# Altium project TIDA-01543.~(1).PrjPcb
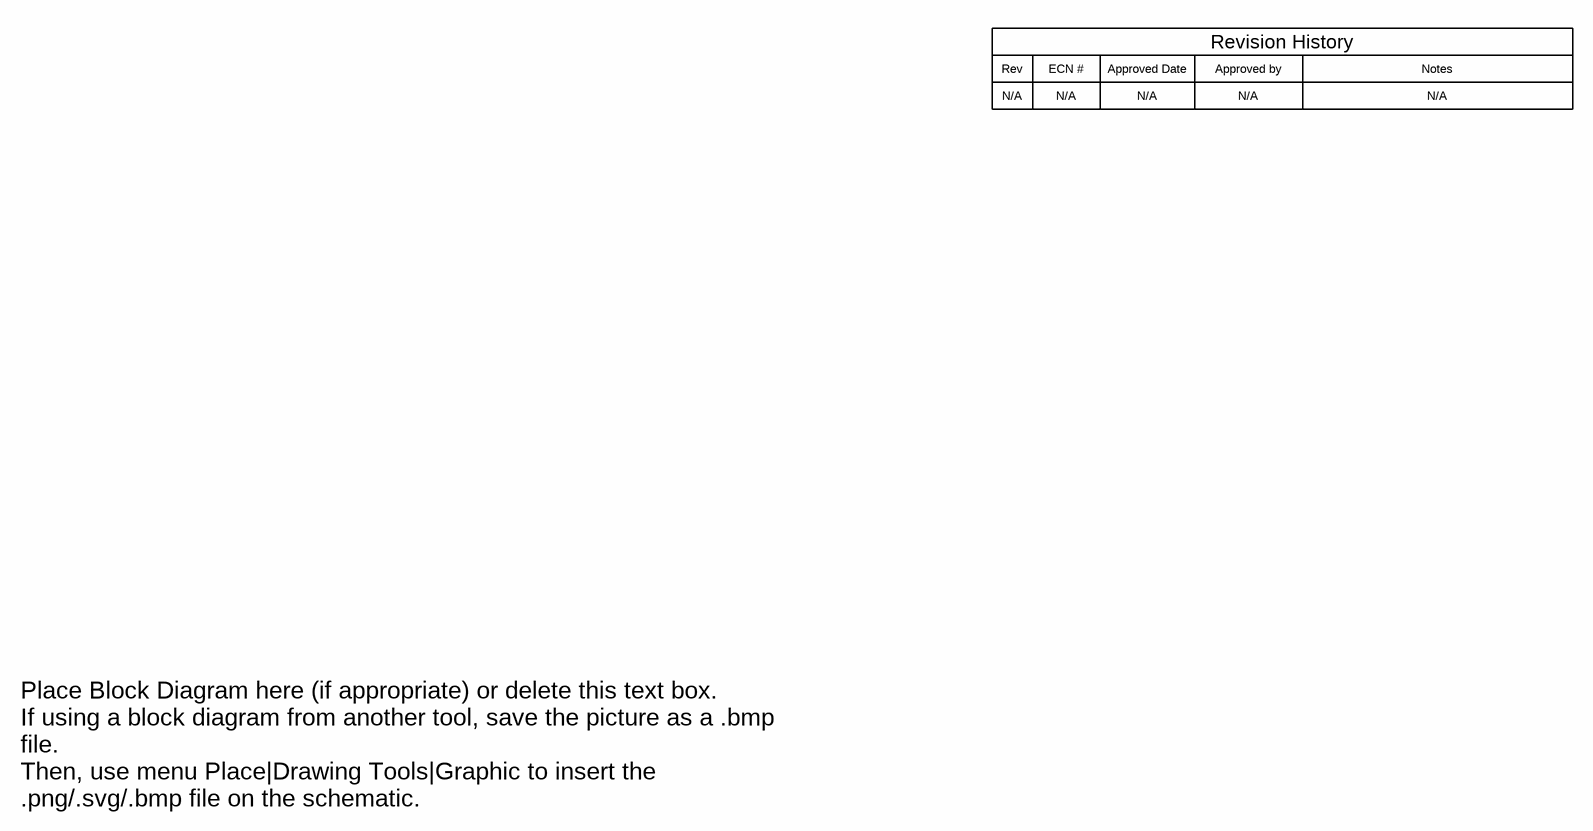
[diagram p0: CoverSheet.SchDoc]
TID: N/A; TechSupport: http://www.ti.com/support; SCH_Rev: E1; PRJ_Title: ±300A Isolated Current Sense for Traction Inverter with Overcurrent Detection; PRJ_Number: TIDA-01543; PRJ_Engineer: S. M.; PRJ_Customer: Public Release; PCB_Rev: A1; PCB_Layout: S. M.; CopyrightYear: 2017
3 sheets, 59 parts. Net scope: flat (ports and power ports of the same name join across sheets).
Board file: PCB.PcbDoc
Sheets:
  CoverSheet.SchDoc
  EVM_Hardware.SchDoc
  EVM_Main.SchDoc

## Sheet CoverSheet.SchDoc
size 431 x 279 mm; Date: Not shown in title block; ApprovedBy: Not shown in title block; CheckedBy: Not shown in title block; Author: Not shown in title block; CompanyName: Not shown in title block; Engineer: Not shown in title block; Organization: Not shown in title block; Address1: Not shown in title block; Address2: Not shown in title block; Address3: Not shown in title block; Address4: Not shown in title block; DocumentNumber: 1; Revision: Use project parameter SCH_Rev; SheetNumber: 1; SheetTotal: 3; PageSetup: Record=PageOptions¦CenterHorizontal=True¦CenterVertical=True¦PrintScale=1.00¦XCorrection=1.00¦YCorrection=1.00¦PrintKind=0¦BorderSize=5000000¦LeftOffset=0¦BottomOffset=0¦Orientation=2¦PaperLength=1000¦PaperWidth=1000¦Scale=100¦PaperSource=15¦PrintQuality=600¦MediaType=1¦DitherType=10¦PaperKind=Letter¦PrintScaleMode=1

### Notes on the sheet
- Rev
- N/A
- ECN #
- Approved Date
- Approved by
- Revision History
- Notes
- Place Block Diagram here (if appropriate) or delete this text box.
  If using a block diagram from another tool, save the picture as a .bmp file.
  Then, use menu Place|Drawing Tools|Graphic to insert the .png/.svg/.bmp file on the schematic.

## Sheet EVM_Hardware.SchDoc
size 431 x 279 mm; Date: Not shown in title block; ApprovedBy: Not shown in title block; CheckedBy: Not shown in title block; Author: Not shown in title block; CompanyName: Not shown in title block; Engineer: Not shown in title block; Organization: Not shown in title block; Address1: Not shown in title block; Address2: Not shown in title block; Address3: Not shown in title block; Address4: Not shown in title block; DocumentNumber: 1; Revision: Use project parameter SCH_Rev; SheetNumber: 3; SheetTotal: 3; PageSetup: Record=PageOptions¦CenterHorizontal=True¦CenterVertical=True¦PrintScale=1.00¦XCorrection=1.00¦YCorrection=1.00¦PrintKind=0¦BorderSize=5000000¦LeftOffset=0¦BottomOffset=0¦Orientation=2¦PaperLength=1000¦PaperWidth=1000¦Scale=100¦PaperSource=15¦PrintQuality=600¦MediaType=1¦DitherType=10¦PaperKind=Letter¦PrintScaleMode=1
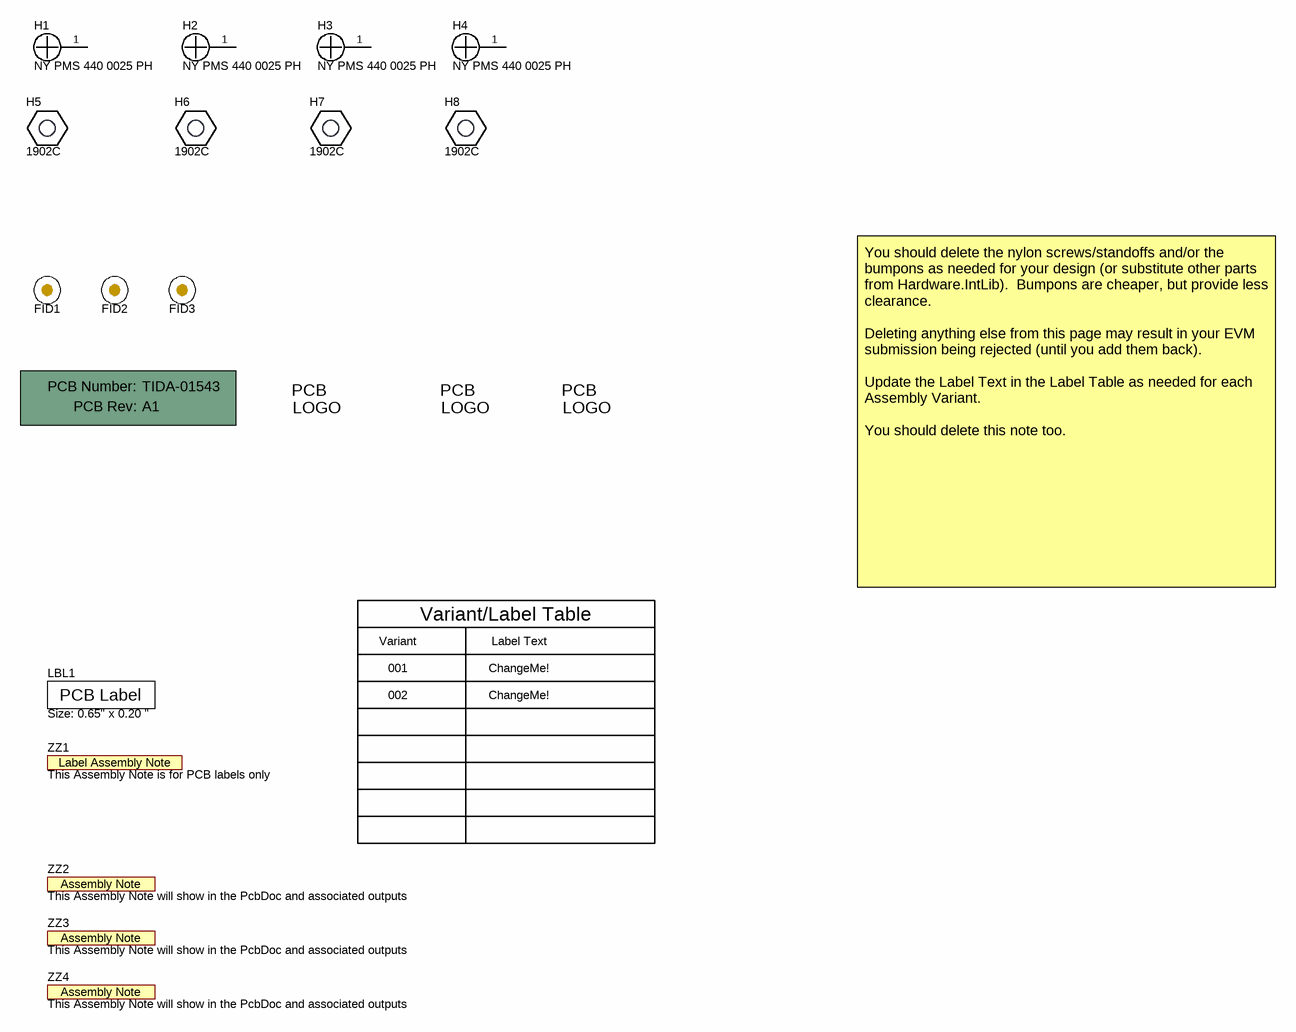
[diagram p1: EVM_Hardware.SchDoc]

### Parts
!PCB1  Printed Circuit Board  (value not drawn)  (mechanical)
FID1  Fiducial  [Fiducial10-20]  (value not drawn)
FID2  Fiducial  [Fiducial10-20]  (value not drawn)
FID3  Fiducial  [Fiducial10-20]  (value not drawn)
H1  NY PMS 440 0025 PH  [NY PMS 440 0025 PH]
H2  NY PMS 440 0025 PH  [NY PMS 440 0025 PH]
H3  NY PMS 440 0025 PH  [NY PMS 440 0025 PH]
H4  NY PMS 440 0025 PH  [NY PMS 440 0025 PH]
H5  1902C  [Keystone_1902C]
H6  1902C  [Keystone_1902C]
H7  1902C  [Keystone_1902C]
H8  1902C  [Keystone_1902C]
LBL1  Size: 0.65" x 0.20 "  [Label_650x200]
Logo1  Texas Instruments  [TI_Stacked_Overlay_Small]  (value not drawn)  (no BOM)
Logo2  Pb-Free Symbol  [Pb-Free_Overlay_Small]  (value not drawn)  (no BOM)
Logo3  FCC disclaimer  [FCC_disclaimer]  (value not drawn)  (no BOM)
ZZ1  This Assembly Note is for PCB labels only  [AssemblyNoteLabel]  (no BOM)
ZZ2  This Assembly Note will show in the PcbDoc and associated outputs  [AssemblyNote]  (no BOM)
ZZ3  This Assembly Note will show in the PcbDoc and associated outputs  [AssemblyNote]  (no BOM)
ZZ4  This Assembly Note will show in the PcbDoc and associated outputs  [AssemblyNote]  (no BOM)

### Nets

Not connected (* = marked no-connect by the designer): H1 1; H2 1; H3 1; H4 1

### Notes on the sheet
- Variant
- Variant/Label Table
- Label Text
- You should delete the nylon screws/standoffs and/or the bumpons as needed for your design (or substitute other parts from Hardware.IntLib).  Bumpons are cheaper, but provide less clearance.
  Deleting anything else from this page may result in your EVM submission being rejected (until you add them back).
  Update the Label Text in the Label Table as needed for each Assembly Variant.
  You should delete this note too.
- 001
- 002
- ChangeMe!

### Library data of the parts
!PCB1 = PCB: Manufacturer: Any; PartNumber: TIDA-01543; SymbolCreator: a0412235
FID1-FID3 = Fiducial: Fiducial mark.  There is nothing to buy or mount.; SymbolCreator: codlsc
H1-H4 = NY PMS 440 0025 PH: Machine Screw, Round, #4-40 x 1/4, Nylon, Philips panhead; Manufacturer: B&F Fastener Supply; CompType: Hardware; SymbolCreator: codlsc; U/M: EA; Green_Lifecycle: Not Set; Green_REACh: Incomplete
H5-H8 = 1902C: Standoff, Hex, 0.5"L #4-40 Nylon; Manufacturer: Keystone; Green_Lifecycle: Active; Green_REACh: Passed; SymbolCreator: a0412235
LBL1 = THT-14-423-10: Thermal Transfer Printable Labels, 0.650" W x 0.200" H - 10,000 per roll; Manufacturer: Brady; SymbolCreator: a0412235; CompType: Label; Green_Lifecycle: Not Set; Green_REACh: Incomplete
Logo1 = TI_Logo: Texas Instrument Corporate Signature; SymbolCreator: a0412235
Logo2 = Pb-Free: SymbolCreator: a0412235
Logo3 = FCC_disclaimer: SymbolCreator: a0412235
ZZ1 = AssemblyNoteLabel: SymbolCreator: a0412235
ZZ2-ZZ4 = AssemblyNote: SymbolCreator: codlsc

## Sheet EVM_Main.SchDoc
size 431 x 279 mm; Date: Not shown in title block; ApprovedBy: Not shown in title block; CheckedBy: Not shown in title block; Author: Not shown in title block; CompanyName: Not shown in title block; Engineer: Not shown in title block; Organization: Not shown in title block; Address1: Not shown in title block; Address2: Not shown in title block; Address3: Not shown in title block; Address4: Not shown in title block; DocumentNumber: 1; Revision: Use project parameter SCH_Rev; SheetNumber: 2; SheetTotal: 3; PageSetup: Record=PageOptions¦CenterHorizontal=True¦CenterVertical=True¦PrintScale=1.00¦XCorrection=1.00¦YCorrection=1.00¦PrintKind=0¦BorderSize=5000000¦LeftOffset=0¦BottomOffset=0¦Orientation=2¦PaperLength=1000¦PaperWidth=1000¦Scale=100¦PaperSource=15¦PrintQuality=600¦MediaType=1¦DitherType=10¦PaperKind=Letter¦PrintScaleMode=1
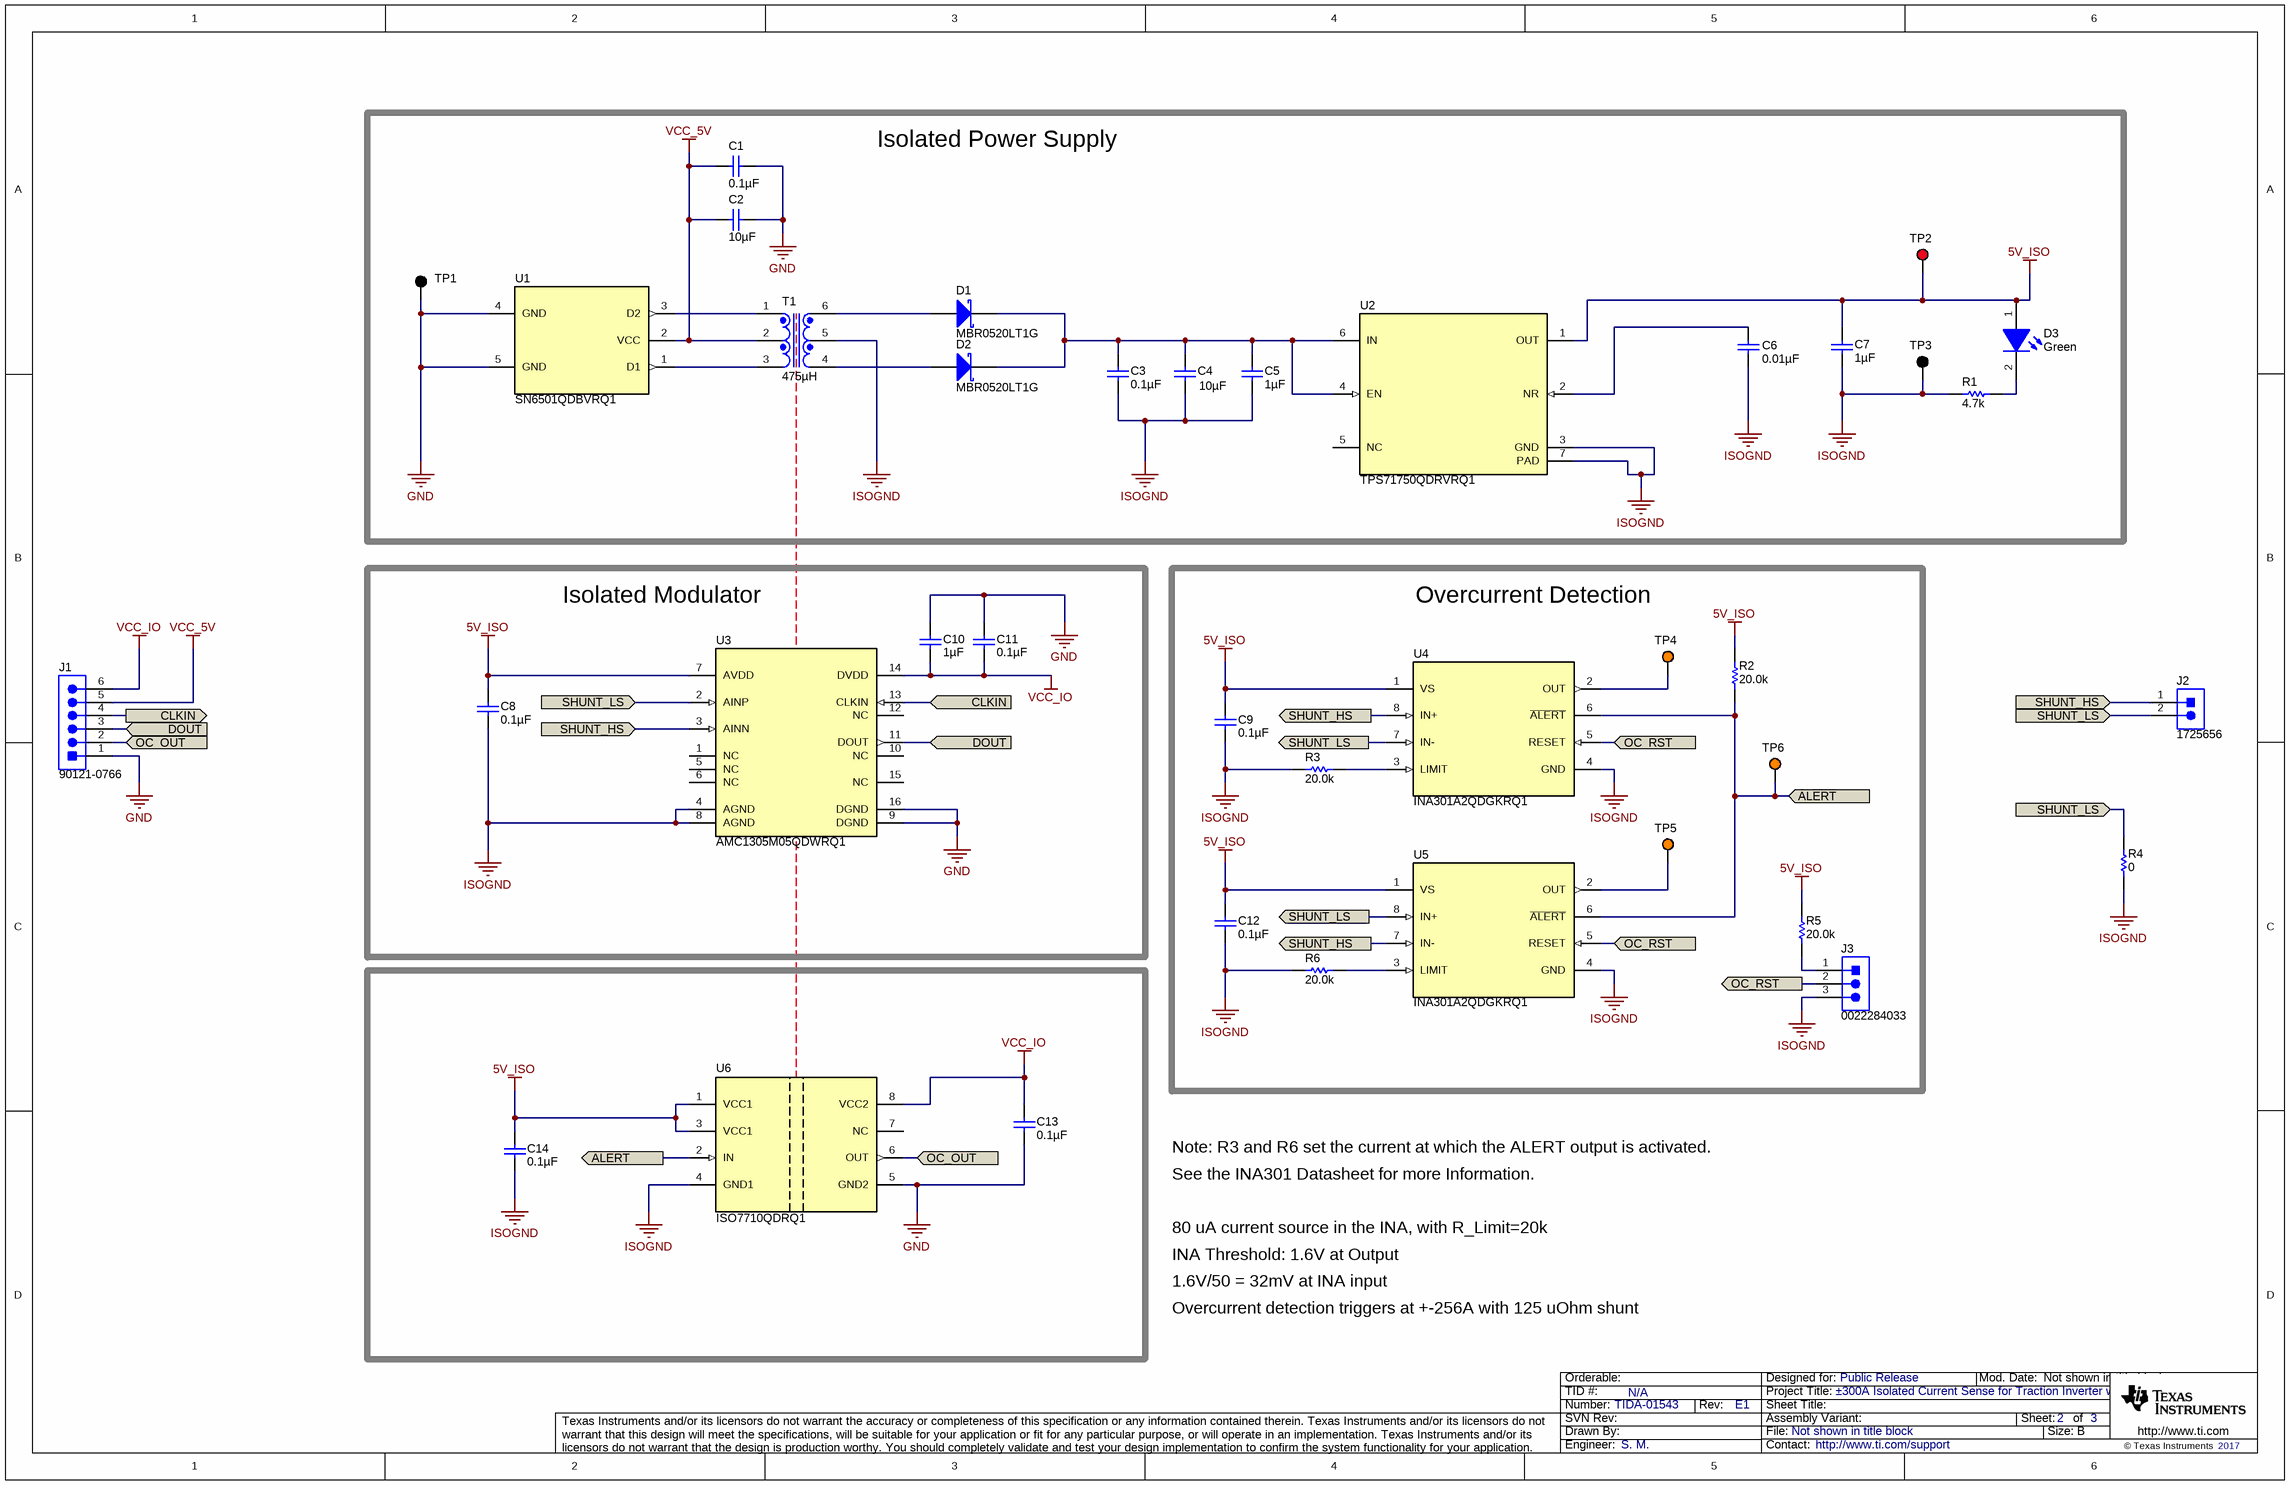
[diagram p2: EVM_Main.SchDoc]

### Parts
C1  ValueDisplayed: 0.1µF  [0603]  (hidden comment: GCM188R71C104KA37J)
C2  ValueDisplayed: 10µF  [1206_180]  (hidden comment: GRM31CR71C106KAC7L)
C3  ValueDisplayed: 0.1µF  [0603]  (hidden comment: GCM188R71C104KA37J)
C4  ValueDisplayed: 10µF  [1206_180]  (hidden comment: GRM31CR71C106KAC7L)
C5  ValueDisplayed: 1µF  [0603]  (hidden comment: GCM188R71C105KA64D)
C6  ValueDisplayed: 0.01µF  [0603]  (hidden comment: GRM188R71C103KA01D)
C7  ValueDisplayed: 1µF  [0603]  (hidden comment: GCM188R71C105KA64D)
C8  ValueDisplayed: 0.1µF  [0603]  (hidden comment: GCM188R71C104KA37J)
C9  ValueDisplayed: 0.1µF  [0603]  (hidden comment: GCM188R71C104KA37J)
C10  ValueDisplayed: 1µF  [0603]  (hidden comment: GRM188R71C105KA12D)
C11  ValueDisplayed: 0.1µF  [0603]  (hidden comment: GCM188R71C104KA37J)
C12  ValueDisplayed: 0.1µF  [0603]  (hidden comment: GCM188R71C104KA37J)
C13  ValueDisplayed: 0.1µF  [0603]  (hidden comment: GCM188R71C104KA37J)
C14  ValueDisplayed: 0.1µF  [0603]  (hidden comment: GCM188R71C104KA37J)
D1  MBR0520LT1G  [SOD-123]
D2  MBR0520LT1G  [SOD-123]
D3  value Green  [LG L29K_GREEN]  (hidden comment: LG L29K-G2J1-24-Z)
J1  90121-0766  [Molex_90121-0766]
J2  1725656  [CONN_1725656]
J3  0022284033  [Molex_0022284033]
R1  ValueDisplayed: 4.7k  [0603]  (hidden comment: CRCW06034K70JNEA)
R2  ValueDisplayed: 20.0k  [0603]  (hidden comment: CRCW060320K0FKEA)
R3  ValueDisplayed: 20.0k  [0603]  (hidden comment: CRCW060320K0FKEA)
R4  ValueDisplayed: 0  [0603]  (hidden comment: CRCW06030000Z0EA)
R5  ValueDisplayed: 20.0k  [0603]  (hidden comment: CRCW060320K0FKEA)
R6  ValueDisplayed: 20.0k  [0603]  (hidden comment: CRCW060320K0FKEA)
T1  ValueDisplayed: 475µH  [Wurth_760390013]  (hidden comment: 760390014)
TP1  5001  [Keystone5001]  (value not drawn)
TP2  5000  [Keystone5000]  (value not drawn)
TP3  5001  [Keystone5001]  (value not drawn)
TP4  5003  [Keystone5003]  (value not drawn)
TP5  5003  [Keystone5003]  (value not drawn)
TP6  5003  [Keystone5003]  (value not drawn)
U1  SN6501QDBVRQ1  [DBV0005A_N]
U2  TPS71750QDRVRQ1  [DRV0006A]
U3  AMC1305M05QDWRQ1  [DW0016B_HV]
U4  INA301A2QDGKRQ1  [DGK0008A_N]
U5  INA301A2QDGKRQ1  [DGK0008A_N]
U6  ISO7710QDRQ1  [D0008B_HV]

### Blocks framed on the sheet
Isolated Power Supply: C1-C7 D1-D3 R1 T1 TP1-TP3 U1 U2
Isolated Modulator: C8 C10 C11 U3
Overcurrent Detection: C9 C12 J3 R2 R3 R5 R6 TP4-TP6 U4 U5

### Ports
ALERT, CLKIN, CLKIN (in), DOUT (in), OC_OUT, OC_RST, SHUNT_HS, SHUNT_LS

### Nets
5V_ISO: C7.1 C8.1 C9.1 C12.1 C14.1 D3.1(A) R2.2 R5.2 TP2.1 U2.1(OUT) U3.7(AVDD) U4.1(VS) U5.1(VS) U6.1(VCC1) U6.3(VCC1)
GND: C1.1 C2.2 C10.1 C11.1 C13.2 J1.1 TP1.1 U1.4(GND) U1.5(GND) U3.9(DGND) U3.16(DGND) U6.5(GND2)
ISOGND: C3.2 C4.2 C5.2 C6.2 C7.2 C8.2 C9.2 C12.2 C14.2 J3.3 R1.1 R3.1 R4.1 R6.1 T1.5 TP3.1 U2.3(GND) U2.7(PAD) U3.4(AGND) U3.8(AGND) U4.4(GND) U5.4(GND) U6.4(GND1)
VCC_5V: C1.2 C2.1 J1.5 T1.2 U1.2(VCC)
VCC_IO: C10.2 C11.2 C13.1 J1.6 U3.14(DVDD) U6.8(VCC2)
ALERT: R2.1 TP6.1 U4.6(~{ALERT}) U5.6(~{ALERT}) U6.2(IN) ; port ALERT
CLKIN: J1.4 U3.13(CLKIN) ; port CLKIN
DOUT: J1.3 U3.11(DOUT) ; port DOUT
OC_OUT: J1.2 U6.6(OUT) ; port OC_OUT
OC_RST: J3.2 U4.5(RESET) U5.5(RESET) ; port OC_RST
SHUNT_HS: J2.1 U3.3(AINN) U4.8(IN+) U5.7(IN-) ; port SHUNT_HS
SHUNT_LS: J2.2 R4.2 U3.2(AINP) U4.7(IN-) U5.8(IN+) ; port SHUNT_LS
NetC3_1: C3.1 C4.1 C5.1 D1.1(K) D2.1(K) U2.4(EN) U2.6(IN)
NetC6_1: C6.1 U2.2(NR)
NetD1_2: D1.2(A) T1.6
NetD2_2: D2.2(A) T1.4
NetD3_2: D3.2(K) R1.2
NetJ3_1: J3.1 R5.1
NetR3_2: R3.2 U4.3(LIMIT)
NetR6_2: R6.2 U5.3(LIMIT)
NetT1_1: T1.1 U1.3(D2)
NetT1_3: T1.3 U1.1(D1)
NetTP4_1: TP4.1 U4.2(OUT)
NetTP5_1: TP5.1 U5.2(OUT)

Not connected (* = marked no-connect by the designer): U2 5(NC); U3 1(NC) 5(NC) 6(NC) 10(NC) 12(NC) 15(NC); U6 7(NC)

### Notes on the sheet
- Note: R3 and R6 set the current at which the ALERT output is activated.
- See the INA301 Datasheet for more Information.
- 80 uA current source in the INA, with R_Limit=20k
- INA Threshold: 1.6V at Output
- 1.6V/50 = 32mV at INA input
- Overcurrent detection triggers at +-256A with 125 uOhm shunt

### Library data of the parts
C1 C3 C8 C9 C11-C14 = GCM188R71C104KA37J: CAP, CERM, 0.1 µF, 16 V,+/- 10%, X7R, AEC-Q200 Grade 1, 0603; Manufacturer: MuRata; Polarized: N; CompType: Capacitor; Value: 0.1uF; U/M: EA; Cap_F: 0.0000001; Tolerance_%: 10; Value1: Unknown; VDC_V: 16; Value2: 16V; TaMin_C: -55; TaMax_C: 125; SizeArea_mm2: 1.28; SizeAreaWB_mm2: 4.68; SizeX_mm: 1.6; SizeY_mm: 0.8; SizeZ_mm: 1; AEC Category: Q200; AEC Qualified: Y; Green_Lifecycle: Active; Green_REACh: Passed
C2 C4 = GRM31CR71C106KAC7L: CAP, CERM, 10 µF, 16 V,+/- 10%, X7R, 1206; Manufacturer: MuRata; Polarized: N; CompType: Capacitor; Value: 10uF; U/M: EA; Cap_F: 0.00001; Tolerance_%: 10; Value1: Unknown; VDC_V: 16; Value2: 16V; TaMin_C: -55; TaMax_C: 125; Cap_Case: 1206; SizeArea_mm2: 5.12; SizeAreaWB_mm2: 10.92; SizeX_mm: 3.2; SizeY_mm: 1.6; SizeZ_mm: 1.8; AEC Category: Q200; Green_Lifecycle: Active; Green_REACh: Passed
C5 C7 = GCM188R71C105KA64D: CAP, CERM, 1 µF, 16 V,+/- 10%, X7R, AEC-Q200 Grade 1, 0603; Manufacturer: MuRata; Polarized: N; CompType: Capacitor; Value: 1uF; U/M: EA; Cap_F: 0.000001; Tolerance_%: 10; Value1: Unknown; VDC_V: 16; Value2: 16V; TaMin_C: -55; TaMax_C: 125; SizeArea_mm2: 1.28; SizeAreaWB_mm2: 4.68; SizeX_mm: 1.6; SizeY_mm: 0.8; SizeZ_mm: 1; AEC Category: Q200; AEC Qualified: Y; Green_Lifecycle: Active; Green_REACh: Passed
C6 = GRM188R71C103KA01D: CAP, CERM, 0.01 µF, 16 V,+/- 10%, X7R, 0603; Manufacturer: MuRata; Polarized: N; CompType: Capacitor; Value: 0.01uF; U/M: EA; Cap_F: 0.00000001; Tolerance_%: 10; Value1: Unknown; VDC_V: 16; Value2: 16V; TaMin_C: -55; TaMax_C: 125; SizeArea_mm2: 1.28; SizeAreaWB_mm2: 4.68; SizeX_mm: 1.6; SizeY_mm: 0.8; SizeZ_mm: 1; AEC Category: Q200; Green_Lifecycle: Active; Green_REACh: Passed
C10 = GRM188R71C105KA12D: CAP, CERM, 1 µF, 16 V,+/- 10%, X7R, 0603; Manufacturer: MuRata; Polarized: N; CompType: Capacitor; Value: 1uF; U/M: EA; Cap_F: 0.000001; Tolerance_%: 10; ESR_ohm: 0.011; Value1: 0.011 ohm; VDC_V: 16; Value2: 16V; TaMin_C: -55; TaMax_C: 125; SizeArea_mm2: 1.28; SizeAreaWB_mm2: 4.68; SizeX_mm: 1.6; SizeY_mm: 0.8; SizeZ_mm: 1; AEC Category: Q200; Green_Lifecycle: Active; Green_REACh: Passed
D1 D2 = MBR0520LT1G: Diode, Schottky, 20 V, 0.5 A, SOD-123; Manufacturer: ON Semiconductor; U/M: EA; Vf_V: 0.385; Value: 20V; Value1: 0.5A; Value2: 0.385V; Io_A: 0.5; Vr_V: 20; TJmax_C: 125; RJC_CperW: 150; SizeAreaWB_mm2: 13.095; SizeArea_mm2: 6.545; SizeX_mm: 3.85; SizeY_mm: 1.7; SizeZ_mm: 1.35; AEC Category: Q101; Green_Lifecycle: Active; Green_REACh: Passed
D3 = LG L29K-G2J1-24-Z: LED, Green, SMD; Manufacturer: OSRAM; Vf_V: 1.7; Value2: 1.7V; Io_A: 0.002; Tjmax_C: 110; Value1: W; U/M: EA; Green_Lifecycle: Not Set; Green_REACh: Incomplete
J1 = 90121-0766: Header, 2.54mm, 6x1, Gold, R/A, TH; Manufacturer: Molex; SymbolCreator: a0412235; Pitch_mm: 2.54; Gender: Male; Shrouded: N; Row_Count: 1; Current_A: 3; Voltage_V: 350; Cert_UL: Y
J2 = 1725656: Terminal Block, 100mil, 2x1, 6A, 63V, TH; Manufacturer: Phoenix Contact; SymbolCreator: a0412235
J3 = 0022284033: Header, 2.54mm, 3x1, Tin, TH; Manufacturer: Molex; SymbolCreator: a0799628; Pitch_mm: 2.54; Gender: Male; Shrouded: N; Row_Count: 1; Current_A: 4; Voltage_V: 250; Cert_UL: Y
R1 = CRCW06034K70JNEA: RES, 4.7 k, 5%, 0.1 W, 0603; Manufacturer: Vishay-Dale; CompType: Resistor; Value: 4.7k; Res_ohm: 4700; Value_Code: 4k70; Tolerance_%: 5; Power_W: 0.1; Value2: 0.1W; VDC_V: 75; TempCo: 200 ppm/C; SizeArea_mm2: 1.28; SizeX_mm: 1.6; SizeY_mm: 0.8; SizeZ_mm: 1; EIA_Code: E24; U/M: EA; AEC Category: Q200; Green_Lifecycle: Active; Green_REACh: Passed
R2 R3 R5 R6 = CRCW060320K0FKEA: RES, 20.0 k, 1%, 0.1 W, 0603; Manufacturer: Vishay-Dale; CompType: Resistor; Value: 20.0k; Res_ohm: 20000; Value_Code: 20k0; Tolerance_%: 1; Power_W: 0.1; Value2: 0.1W; VDC_V: 75; TempCo: 100 ppm/C; SizeArea_mm2: 1.28; SizeX_mm: 1.6; SizeY_mm: 0.8; EIA_Code: E96; U/M: EA; AEC Category: Q200; Green_Lifecycle: Active; Green_REACh: Passed
R4 = CRCW06030000Z0EA: RES, 0, 5%, 0.1 W, 0603; Manufacturer: Vishay-Dale; CompType: Resistor; Value: 0; Value_Code: 0000; Tolerance_%: 5; Power_W: 0.1; Value2: 0.1W; VDC_V: 75; TempCo: 200 ppm/C; SizeArea_mm2: 1.28; SizeX_mm: 1.6; SizeY_mm: 0.8; SizeZ_mm: 1; EIA_Code: E24; U/M: EA; AEC Category: Q200; Green_Lifecycle: Active; Green_REACh: Passed
T1 = 760390014: Transformer, 475uH, SMT; Manufacturer: Wurth Elektronik; SymbolCreator: a0799628; DCR_ohm: 0.31; Lp: 475; Ind_H: 0.000475
TP1 TP3 = 5001: Test Point, Miniature, Black, TH; Manufacturer: Keystone; CompType: Test Point Loop; ContactFinish: Silver; Green_Lifecycle: Active; Green_REACh: Passed
TP2 = 5000: Test Point, Miniature, Red, TH; Manufacturer: Keystone; CompType: Test Point Loop; ContactFinish: Silver; Green_Lifecycle: Active; Green_REACh: Passed
TP4-TP6 = 5003: Test Point, Miniature, Orange, TH; Manufacturer: Keystone; CompType: Test Point Loop; ContactFinish: Silver; Green_Lifecycle: Active; Green_REACh: Passed
U1 = SN6501QDBVRQ1: Automotive Low-Noise 350 mA, 410 kHz Transformer Driver, DBV0005A (SOT-23-5); Manufacturer: Texas Instruments; SymbolCreator: a0411947; SizeArea_mm2: 8.12; SizeAreaWB_mm2: 14.82; SizeX_mm: 2.8; SizeY_mm: 2.9; SizeZ_mm: 1.45; CompType: IC; U/M: EA
U2 = CMP-0082419-1: Low Noise, High-Bandwidth PSRR Low-Dropout 150mA Linear Regulator for Automotive Applications, DRV0006A (WSON-6); Alternate Manufacturer: Texas Instruments; SizeAreaWB_mm2: 9; SizeZ_mm: 0.8; SizeX_mm: 2; SizeArea_mm2: 4; CompType: IC; AEC Qualified: Y; AEC Category: Q200
U3 = CMP-0082424-1: Automotive Reinforced Isolated Modulator With +/-50mV Input and CMOS Interface, DW0016B (SOIC-16); Alternate PartNumber: AMC1305M05QDWQ1; Alternate Manufacturer: Texas Instruments; SizeAreaWB_mm2: 152.52; SizeZ_mm: 2.65; SizeX_mm: 10.4; SizeY_mm: 10.3; SizeArea_mm2: 107.12; CompType: IC; AEC Qualified: Y; AEC Category: Q200
U4 U5 = CMP-0082409-1: AEC-Q100, 36V, Low-/High-side, Voltage Output CSA with Comparator, DGK0008A (VSSOP-8); Alternate PartNumber: INA301A2QDGKTQ1; Alternate Manufacturer: Texas Instruments; SizeAreaWB_mm2: 23.6; Rating: Automotive; SizeZ_mm: 1.1; SizeX_mm: 4.9; SizeY_mm: 3; SizeArea_mm2: 14.7; CompType: IC; AEC Qualified: Y; AEC Category: Q200
U6 = CMP-0082405-1: Automotive, High Speed, Robust EMC Reinforced Single-Channel Digital Isolator, D0008B (SOIC-8); Alternate PartNumber: ISO7710QDQ1; Alternate Manufacturer: Texas Instruments; SizeAreaWB_mm2: 55.2; SizeZ_mm: 1.75; SizeX_mm: 6; SizeY_mm: 4.9; SizeArea_mm2: 29.4; CompType: IC; AEC Qualified: Y; AEC Category: Q200

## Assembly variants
001: not fitted FID1 FID2 FID3 R3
